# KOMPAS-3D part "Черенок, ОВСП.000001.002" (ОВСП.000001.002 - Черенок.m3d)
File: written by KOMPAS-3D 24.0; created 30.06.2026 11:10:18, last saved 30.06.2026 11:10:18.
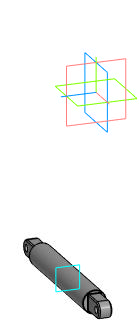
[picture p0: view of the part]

Document properties: Автор: Админ; Полное имя файла: C:\Users\Админ\Documents\ОВСП.000001.002 - Черенок.m3d

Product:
- Part/product: Черенок  | designation ОВСП.000001.002

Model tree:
1. Эскиз:1  (with: Грань.Элемент выдавливания:2, Ребро.Элемент выдавливания:3)
2. Элемент выдавливания:1  (with: Грань.Элемент выдавливания:2)
     Расстояние 1 = 11
3. Фаска:1  (with: Ребро.Элемент выдавливания:1)
     Угол = 45; Длина 1 = 1; Длина 2 = 1
4. Эскиз:2  (with: Грань.Элемент выдавливания:1, Вершина.Фаска:1)
5. Элемент выдавливания:2
     Расстояние 1 = 120
6. Смещенная плоскость:1  (with: Грань.Элемент выдавливания:2)
     Расстояние = 60
7. Фаска:3  (with: Ребро.Элемент выдавливания:2)
     Угол = 45; Длина 1 = 0.5; Длина 2 = 0.5
8. Скругление:2  (with: Ребро.Элемент выдавливания:2)
     Радиус = 0.5
9. Зеркальный массив:2
10. Экземпляр ( 1 )
11. Экземпляр ( 2 )  (with: Элемент выдавливания:1, Фаска:1)
12. Скругление:3  (labels: Ребро.Элемент выдавливания:1.Экземпляр ( 2 ); Ребро.Фаска:1.Экземпляр ( 2 ))
     Радиус = 0.5
13. Фаска:4  (with: Ребро.Элемент выдавливания:2)
     Угол = 45; Длина 1 = 0.5; Длина 2 = 0.5

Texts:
  ОВСП.000001.002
